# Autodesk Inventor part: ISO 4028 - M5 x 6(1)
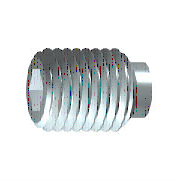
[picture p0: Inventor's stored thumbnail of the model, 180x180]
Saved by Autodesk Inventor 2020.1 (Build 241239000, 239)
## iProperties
Created: 2019-01
Part Number: ISO 4028 - M5 x 6(1)
Material: Edelstahl, 440C
Description: Innensechskant-Gewindestifte mit Zapfen
Document SubType Name: Modeling
Standard: ISO 4028
Designer: lutzd
Standard Revision: Third edition 2003-12-01
Standards Organization: ISO
Language: de-DE
Size Designation: M5 x 6
Categories: <MemberInstance><Categories><Category DisplayName="Verbindungselemente" InternalName="e4da775c-781d-43d5-af7c-5136215cf5a6" Mnemonic="FSTN"><Category DisplayNam
Mass: 0.679458 g
Surface Area: 1.35277 cm^2
Volume: 0.087672 cm^3
Density: 7.75 g/cm^3
Appearance: Halbpoliert
IsCustomPart: 0
Author: lutzd
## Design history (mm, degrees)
sketch "Skizze1"
  geometry: L1 (0, 0)-(3.167, 0); L2 (6, 1.443)-(6, 2.5); L3 (6, 2.5)-(1.25, 2.5); L4 (6, 1.443)-(4, 1.443); L5 (4, 1.443)-(3.167, 0); L6 (0, -0.5)-(0, 3) reference; L7 (0, 1.75)-(0, 0); L8 (0, 1.75)-(1.25, 1.75); L9 (1.25, 1.75)-(1.25, 2.5)
  constraints: 17 end point, 3 parallel, 3 perpendicular, 1 collinear, 1 point on line
  dimensions: "d0" = 2 distance of L2.start L4.end (= INTI); "d1" = 60 deg angle of L5 L1; "d2" = 5 diameter of L3 L1 (= NND); "d3" = 2.88675 diameter of L4 L1 (= 1.1547 x SW); "d5" = 6 distance from line of L2 L7.start (= NLG); "d7" = 3.5 diameter of L7.start L1 (= SPD); "d14" = 1.25 distance of L7.start L8.end (= ZLG)
revolve "Körper" sketch "Skizze1" stored, may be unused: angle "d6" = 90 deg
sketch "Skizze2"
  geometry: L1 (-0.722, 1.25)-(0.722, 1.25); L2 (0.722, 1.25)-(1.443, 0); L3 (1.443, 0)-(0.722, -1.25); L4 (0.722, -1.25)-(-0.722, -1.25); L5 (-0.722, -1.25)-(-1.443, 0); L6 (-1.443, 0)-(-0.722, 1.25); A1 r 1.443 centre (0, 0) between (-0.722, 1.25) and (0.722, 1.25) reference; 2 further points
  constraints: 12 end point, 2 point on circle, 1 coincident, 1 horizontal, 11 other
extrude "Loch" join sketch "Skizze2" taper "d10" = 0 deg; stored distance "d21" = 10
workaxis "Work Axis1"
workplane "Work Plane1"
body "Solid1"
chamfer "Fase1" distance "d8" = 0.28334 (computed from NND, GD1, FAWI); stored, may be unused: angle "d9" = 60 deg (= FAWI), second distance "d30" = 0.28334 (computed from NND, GD1, FAWI)
feature "Gewinde" dims "d12" = 4.75 (= NLG - ZLG), "d13" = 0
chamfer "Fase2" distance "d15" = 0.75 (computed from NND, SPD, FAWI1); stored, may be unused: angle "d16" = 45 deg (= FAWI1), second distance "d31" = 0.75 (computed from NND, SPD, FAWI1)
other parameters: "NND" = 5 [user parameter; used in 5 equation terms], "NLG" = 6 [user parameter; used in 2 equation terms], "INTI" = 2 [user parameter; used in 1 equation term], "FAWI" = 60 deg [user parameter; used in 3 equation terms], "SW" = 2.5 [user parameter; used in 2 equation terms], "GD1" = 4.01848 (= THREADDIA - 1.2269 x PTC) [user parameter; used in 2 equation terms], "d4" = 0, "FAWI1" = 45 deg [user parameter; used in 3 equation terms], "SPD" = 3.5 [user parameter; used in 3 equation terms], "ZLG" = 1.25 [user parameter; used in 2 equation terms], "d32" = 0, "d33" = 0, "GUL" = 0.49076 (= 0.61345 x PTC) [user parameter], "TPU" = 12.5 (computed from PTC) [user parameter], "TOA" = 30 deg [user parameter], "THREADDIA" = 5 [user parameter; used in 1 equation term], "PTC" = 0.8 [user parameter; used in 4 equation terms], "GAL" = 0.49076 (= 0.61345 x PTC) [user parameter], "E0" = 2.8875 (= 1.155 x SW) [user parameter]
